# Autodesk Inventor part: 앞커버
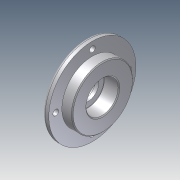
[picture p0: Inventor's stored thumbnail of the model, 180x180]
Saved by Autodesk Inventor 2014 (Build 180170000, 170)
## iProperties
Company: 한국ATC센터
Created: 2014-01
Part Number: 앞커버
Document SubType Name: Modeling
Designer: KYOUNG IL JANG
Density: 1 g/cm^3
Material: 강철, 연강
Mass: 88.8969 g
Surface Area: 235.103 cm^2
Volume: 88.8969 cm^3
Vendor: CBT Solutions
Appearance: 강철
Author: KYOUNG IL JANG
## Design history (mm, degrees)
sketch "스케치1"
  geometry: L1 (-15, -35)-(-15, 35) reference; L2 (-15, 35)-(67, 35) reference; L3 (-3, 25)-(-3, -10.613) reference; L4 (0, 0)-(-32, 0); L5 (-3, 0)-(-3, 35); L6 (-3, 35)-(-15, 35); L7 (-15, 35)-(-15, 50); L8 (-15, 50)-(-22, 50); L9 (-22, 50)-(-22, 22.5); L10 (-22, 22.5)-(-32, 22.5); L11 (-32, 22.5)-(-32, 0); L12 (-3, 18.5)-(-20, 18.5); L13 (-20, 18.5)-(-20, 12.5); L14 (-20, 12.5)-(-24, 12.5); L15 (-24, 12.5)-(-24, 16); L16 (-24, 16)-(-32, 16)
  constraints: 28 end point, 7 perpendicular, 6 parallel, 5 point on line, 1 horizontal, 1 other
  dimensions: "d0" = 7 distance of L7.end L8.end; "d1" = 45 diameter of L10 L4; "d2" = 10 distance of L9.end L10.end; "d3" = 37 diameter of L12 L4; "d4" = 17 distance of L12.start L12.end; "d5" = 32 diameter of L16 L4; "d6" = 8 distance of L15.end L16.end; "d7" = 25 diameter of L14 L4; "d8" = 100 diameter of L8 L4
revolve "회전1" sketch "스케치1" stored, may be unused: angle "d9" = 90 deg
fillet "모깎기1" dims "d10" = 3, "d11" = 0.3
chamfer "모따기1" distance "d12" = 1; stored, may be unused: second distance "d13" = 2, angle "d14" = 45 deg
sketch "스케치2"
  geometry: 2 further points
  constraints: 1 vertical alignment
  dimensions: "d15" = 42 distance of point (0, 0) point (0, 42)
hole "구멍1" sketch "스케치2" at (0, 42) diameter "d16" = 6.6; stored, may be unused: countersink angle "d20" = 90 deg, drill point angle "d22" = 118 deg; dims "d17" = 6, "d18" = 4, "d19" = 2, "d21" = 8
node "솔리드1"
pattern_circular "원형 패턴1" dims angle "d24" = 360 deg
node "참조1"
node "참조2"
